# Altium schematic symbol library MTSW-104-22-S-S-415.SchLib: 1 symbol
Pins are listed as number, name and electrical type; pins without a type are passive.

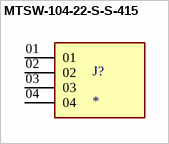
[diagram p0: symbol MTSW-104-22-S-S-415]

## MTSW-104-22-S-S-415
designator J?
MP: MTSW-104-22-S-S-415
footprint SAMTEC_MTSW-104-22-S-S-415
pins: 01, 02, 03, 04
